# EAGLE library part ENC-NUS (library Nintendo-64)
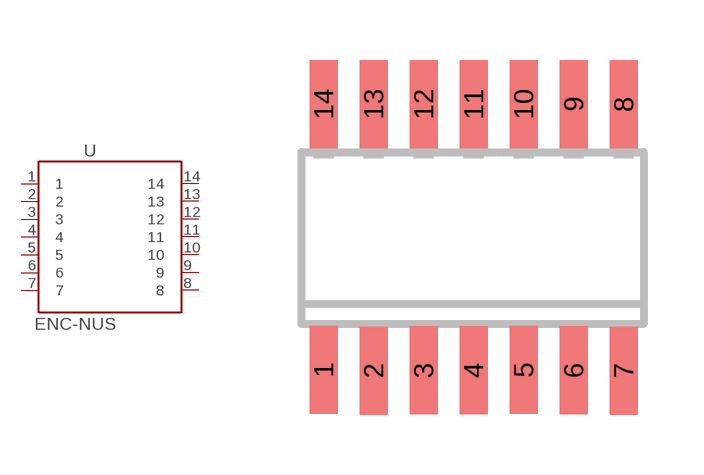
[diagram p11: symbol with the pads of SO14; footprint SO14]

Designator prefix -

## ENC-NUS  [SO14]
1  1
2  2
3  3
4  4
5  5
6  6
7  7
8  8
9  9
10  10
11  11
12  12
13  13
14  14

## Footprint SO14 (pad centres in mm)
smd 0.7 x 2.2: 1 -3.85,-3.295; 2 -2.6,-3.315; 3 -1.35,-3.31; 4 -0.1,-3.305; 5 1.15,-3.295; 6 2.4,-3.31; 7 3.65,-3.315; 8 3.65,3.345; 9 2.4,3.35; 10 1.15,3.35; 11 -0.1,3.35; 12 -1.35,3.35; 13 -2.6,3.35; 14 -3.85,3.35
